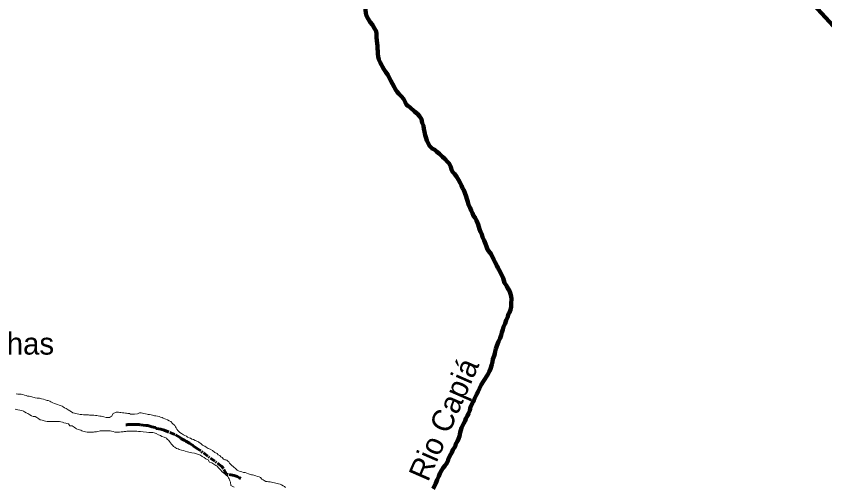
# Model space of a CAD drawing. Extents: x 553962 to 842807, y 8883888 to 9032388.
# Drawn here: x 638188 to 656600, y 8933785 to 8944498 of the extents above; entities that cross this region are included whole.
import ezdxf
from ezdxf.enums import TextEntityAlignment as Align

# ---------------------------------------------------------------- set-up
doc = ezdxf.new("R2010")
doc.units = 0
doc.header["$LTSCALE"] = 20
doc.linetypes.add('LONG_DASH_SHORT_DASH', pattern=[9.9, 6, -1.2, 1.5, -1.2])
for name, color, linetype, lineweight in [('24', 7, 'Continuous', 25), ('25', 7, 'Continuous', 13), ('7', 7, 'LONG_DASH_SHORT_DASH', 60), ('9', 7, 'Continuous', 90)]:
    doc.layers.add(name, color=color, linetype=linetype, lineweight=lineweight)
doc.layers.add('41', color=7, linetype='Continuous')
doc.layers.add('49', color=7, linetype='Continuous')

msp = doc.modelspace()

# ---------------------------------------------------------------- linework, layer by layer
at = {"layer": '24', "lineweight": 53}
for points in [[(645925.12, 8945520.2), (645980.33, 8945480.9), (646030.31, 8945430.92), (646080.29, 8945396.31), (646111.05, 8945361.71), (646137.05, 8945322.55), (646171.76, 8945257.32), (646176.44, 8945189.75), (646181.13, 8945124.68), (646180.83, 8945062.14), (646173.07, 8945007.14), (646162.77, 8944947.15), (646155.03, 8944897.15), (646149.78, 8944847.14), (646141.94, 8944777.13), (646139.17, 8944722.11), (646138.8, 8944644.55), (646145.93, 8944566.96), (646168.16, 8944506.8), (646200.33, 8944434.08), (646247.5, 8944358.79), (646299.76, 8944300.97), (646309.04, 8944284.67)], [(646309.04, 8944284.67), (646346.9, 8944218.17), (646384.15, 8944160.44), (646391.35, 8944097.85), (646395.94, 8944012.77), (646398.11, 8943942.7), (646405.28, 8943872.61), (646412.53, 8943820.04), (646414.72, 8943754.98), (646419.47, 8943702.41), (646424.16, 8943637.34), (646428.88, 8943577.27), (646446.08, 8943512.14), (646475.77, 8943444.43), (646508.03, 8943389.22), (646527.83, 8943344.09), (646562.59, 8943288.87), (646604.79, 8943221.1), (646647.03, 8943160.83), (646684.29, 8943105.6), (646721.45, 8943027.85), (646756.13, 8942957.62), (646790.83, 8942889.89), (646825.57, 8942829.66), (646865.36, 8942779.42), (646902.65, 8942731.69), (646957.43, 8942676.36), (647012.13, 8942606.03), (647046.83, 8942538.29), (647076.57, 8942480.6), (647102.87, 8942459.02), (647151.91, 8942424.72), (647151.91, 8942424.72), (647259.79, 8942331.62), (647323.54, 8942272.81), (647367.67, 8942218.91), (647416.71, 8942155.21), (647431.42, 8942071.9), (647460.84, 8942003.3), (647470.65, 8941934.69), (647485.36, 8941866.09), (647498.58, 8941792.88), (647513.35, 8941742.76), (647537.99, 8941665.08), (647557.79, 8941619.94), (647597.47, 8941547.18), (647657.21, 8941484.32), (647722.12, 8941453.96), (647761.99, 8941421.23), (647826.78, 8941368.35), (647896.49, 8941297.93), (647948.8, 8941250.12), (648011.02, 8941182.25), (648043.36, 8941142.05), (648083.05, 8941071.79), (648100.23, 8941001.64), (648132.5, 8940948.93), (648170.89, 8940907.91), (648214.19, 8940849.18), (648257.5, 8940775), (648294.61, 8940700.82), (648325.54, 8940642.09), (648353.38, 8940586.46), (648378.12, 8940533.92), (648399.77, 8940478.28), (648430.7, 8940394.83), (648446.16, 8940342.28), (648474, 8940274.29), (648489.19, 8940201.48), (648521.39, 8940133.76), (648546.12, 8940073.58), (648581.1, 8940014.64), (648600.57, 8939953.47), (648636.74, 8939906.2), (648667.35, 8939850.59), (648703.52, 8939758.83), (648725.78, 8939700.43), (648739.7, 8939647.6), (648761.96, 8939591.99), (648787, 8939533.6), (648806.47, 8939466.86), (648845.43, 8939394.57), (648873.25, 8939316.71), (648898.3, 8939255.54), (648922.16, 8939185.89), (648969.36, 8939115.59), (649001.71, 8939077.89), (649063.65, 8938952.46), (649095.88, 8938889.74), (649130.59, 8938824.5), (649157.85, 8938769.32), (649200.01, 8938691.53), (649276.83, 8938536), (649291.59, 8938483.38), (649308.84, 8938428.24), (649356.03, 8938355.43), (649380.8, 8938302.76), (649415.62, 8938260.04), (649432.83, 8938197.4), (649457.51, 8938124.71), (649458.67, 8938112.5)], [(649458.67, 8938112.5), (649462.27, 8938074.64), (649461.66, 8937947.03), (649458.86, 8937884.49), (649441.02, 8937814.52), (649418.21, 8937754.59), (649392.98, 8937709.68), (649382.71, 8937654.69), (649342.3, 8937574.82), (649321.94, 8937502.37), (649286.55, 8937427.48), (649266.23, 8937362.53), (649243.4, 8937297.59), (649233.11, 8937237.59), (649207.74, 8937165.16), (649172.36, 8937090.28), (649131.85, 8936990.4), (649111.54, 8936927.95), (649091.23, 8936868), (649088.51, 8936820.47), (649070.74, 8936768.02), (649042.86, 8936693.09), (649035.06, 8936630.58), (649014.73, 8936565.63), (648986.77, 8936473.19), (648966.49, 8936418.24), (648928.61, 8936343.37), (648898.37, 8936298.49), (648858.03, 8936233.64), (648830.29, 8936188.74), (648774.84, 8936103.95), (648736.93, 8936024.08), (648704.07, 8935954.18), (648671.23, 8935886.79), (648635.88, 8935819.41), (648605.56, 8935757.01), (648582.34, 8935707.89)], [(648582.34, 8935707.89), (648534.77, 8935604.74), (648516.88, 8935524.76), (648484.02, 8935454.87), (648466.23, 8935397.41), (648428.44, 8935342.55), (648410.68, 8935290.1), (648377.89, 8935235.22), (648347.58, 8935175.32), (648327.32, 8935125.38), (648299.31, 8935022.93), (648281.39, 8934937.94), (648258.59, 8934878.01), (648238.32, 8934825.56), (648200.51, 8934765.7), (648180.18, 8934700.75), (648132.3, 8934628.43), (648104.46, 8934563.51), (648085.85, 8934528.52)], [(648085.85, 8934528.52), (648033.75, 8934426.25), (648013.45, 8934366.3), (647988.18, 8934313.88), (647947.91, 8934264.04), (647910.14, 8934214.19), (647874.84, 8934156.82), (647836.97, 8934086.95), (647811.67, 8934027.03), (647776.23, 8933942.13), (647745.84, 8933864.72), (647682.69, 8933739.93)]]:
    msp.add_lwpolyline(points, dxfattribs=at)
at = {"layer": '25'}
for points in [[(638186.91, 8935898.35), (638226.9, 8935895.58), (638259.41, 8935895.37), (638281.92, 8935895.22), (638301.93, 8935895.09), (638341.89, 8935887.31), (638376.81, 8935874.57), (638414.23, 8935861.8), (638449.17, 8935851.55), (638486.64, 8935846.3), (638509.11, 8935841.14), (638544.09, 8935835.9), (638566.52, 8935825.74), (638599, 8935820.52), (638621.45, 8935812.86), (638663.91, 8935805.07), (638701.38, 8935799.81), (638721.39, 8935799.68), (638761.31, 8935786.9), (638808.77, 8935779.08), (638851.17, 8935763.77), (638891.11, 8935753.49), (638913.6, 8935750.84), (638950.98, 8935733.07), (638978.38, 8935717.87), (639020.76, 8935700.06), (639058.16, 8935684.79), (639103.07, 8935669.48), (639130.48, 8935656.78), (639170.42, 8935646.5), (639195.36, 8935636.32), (639232.74, 8935618.55), (639260.15, 8935605.85), (639289.99, 8935583.12), (639327.38, 8935565.35), (639349.81, 8935555.19), (639374.67, 8935534.99), (639412.01, 8935512.21), (639444.39, 8935494.48), (639481.73, 8935471.69), (639519.15, 8935458.93), (639544.1, 8935451.26), (639576.56, 8935443.53), (639614.04, 8935438.28), (639646.51, 8935433.05), (639686.49, 8935427.78), (639718.98, 8935425.06), (639738.99, 8935424.93), (639761.5, 8935424.78), (639783.99, 8935422.13), (639814, 8935421.93), (639834.01, 8935421.8), (639856.49, 8935419.14), (639888.99, 8935416.42), (639921.48, 8935413.71), (639956.5, 8935413.48), (639991.47, 8935408.24), (640021.47, 8935405.53), (640053.94, 8935400.32), (640093.9, 8935392.54), (640126.39, 8935389.82), (640148.86, 8935384.67), (640183.82, 8935376.92), (640233.65, 8935364.21), (640316.29, 8935366.03), (640339.19, 8935375.1), (640361.46, 8935385.76), (640394.47, 8935450.64), (640447.22, 8935480.33), (640467.27, 8935485.2), (640487.28, 8935485.07), (640514.77, 8935482.39), (640549.76, 8935479.65), (640572.23, 8935474.49), (640607.22, 8935471.76), (640639.7, 8935466.54), (640677.2, 8935463.78), (640699.69, 8935461.13), (640732.16, 8935455.91), (640767.14, 8935450.67), (640789.57, 8935440.51), (640822.04, 8935435.29), (640842.05, 8935435.15), (640864.56, 8935435.01), (640884.57, 8935434.87), (640947.19, 8935446.98), (640994.86, 8935466.69), (641014.87, 8935466.56), (641037.38, 8935466.41), (641067.35, 8935461.2), (641089.8, 8935453.55), (641132.26, 8935445.75), (641167.23, 8935440.51), (641189.69, 8935432.85), (641224.66, 8935427.62), (641259.62, 8935419.87)], [(638992.5, 8935272.15), (638969.99, 8935272.3), (638924.97, 8935272.59), (638897.48, 8935275.28), (638854.98, 8935278.07), (638825.03, 8935285.77), (638777.64, 8935303.61), (638737.68, 8935311.39), (638700.32, 8935331.66), (638658.05, 8935364.48), (638618.17, 8935382.28), (638573.19, 8935387.58), (638535.79, 8935402.85), (638495.93, 8935423.14), (638451.12, 8935450.98), (638413.76, 8935471.25), (638376.38, 8935489.02), (638351.5, 8935506.71), (638314.1, 8935521.98), (638274.14, 8935529.75), (638224.18, 8935537.6), (638161.77, 8935553.03)], [(641259.62, 8935419.87), (641294.59, 8935414.64), (641334.54, 8935404.36), (641369.51, 8935399.12), (641409.49, 8935393.85), (641441.92, 8935383.62), (641474.32, 8935368.39), (641514.3, 8935363.11), (641536.68, 8935345.44), (641574.08, 8935330.17), (641596.55, 8935325.02), (641636.43, 8935307.23), (641673.81, 8935289.46), (641708.69, 8935271.7), (641748.34, 8935223.87), (641798.06, 8935183.49), (641812.8, 8935148.34), (641832.63, 8935125.67), (641842.45, 8935100.58), (641872.21, 8935067.83), (641894.57, 8935047.65), (641916.88, 8935022.48), (641954.25, 8935002.2), (641994.04, 8934971.89), (642028.91, 8934954.14), (642063.8, 8934936.38), (642086.17, 8934918.71), (642126.04, 8934898.42), (642160.99, 8934890.67), (642188.37, 8934872.97), (642225.79, 8934860.2), (642260.67, 8934842.45), (642283.1, 8934832.29), (642318.02, 8934819.54), (642340.47, 8934811.88), (642357.83, 8934791.74), (642395.17, 8934768.96), (642427.43, 8934736.19), (642462.3, 8934715.94), (642484.75, 8934708.28), (642517.13, 8934690.54), (642539.52, 8934675.37), (642561.91, 8934660.2), (642604.3, 8934642.4), (642661.57, 8934609.47), (642711.25, 8934564.08), (642766.12, 8934543.69), (642790.9, 8934513.48), (642825.78, 8934495.73), (642845.6, 8934470.56), (642875.46, 8934450.33), (642907.72, 8934417.57), (642942.62, 8934402.32), (642965.13, 8934402.17), (642987.58, 8934394.51), (643004.88, 8934366.86), (643027.31, 8934356.7), (643044.57, 8934324.04), (643084.3, 8934286.22), (643146.43, 8934233.24), (643183.71, 8934202.95), (643220.96, 8934167.65), (643253.36, 8934152.42), (643288.22, 8934132.15), (643323.18, 8934124.42), (643363.12, 8934114.14), (643405.59, 8934108.85), (643440.51, 8934096.1), (643477.93, 8934083.33), (643500.39, 8934075.67), (643542.79, 8934060.37), (643567.76, 8934055.2), (643602.75, 8934052.47), (643647.64, 8934034.65), (643685.04, 8934019.38), (643717.47, 8934009.15), (643749.88, 8933993.91), (643784.62, 8933958.64), (643814.52, 8933943.42), (643836.89, 8933925.74), (643871.73, 8933902.98), (643899.25, 8933902.8), (643936.74, 8933900.05), (643971.73, 8933897.31), (644004.21, 8933892.09), (644026.66, 8933884.43), (644066.62, 8933876.65), (644096.57, 8933868.95), (644136.55, 8933863.67), (644161.5, 8933856), (644196.42, 8933843.25), (644226.34, 8933830.53), (644263.7, 8933810.26), (644301.06, 8933789.98), (644323.44, 8933772.31)], [(642690.02, 8934297.16), (642645.24, 8934327.5), (642587.87, 8934347.91), (642556.41, 8934400.24), (642504.77, 8934424.32), (642466.9, 8934451.84), (642425.59, 8934475.92), (642384.28, 8934503.44), (642339.53, 8934524.08), (642294.78, 8934534.4), (642294.78, 8934534.4), (642246.58, 8934548.16), (642188.06, 8934561.92), (642151.83, 8934566.09), (642086.9, 8934579.04), (642032.01, 8934596.93), (641994.61, 8934612.2), (641952.15, 8934619.99), (641902.25, 8934635.34), (641874.87, 8934653.05), (641834.89, 8934658.32), (641800.09, 8934686.08), (641770.19, 8934701.3), (641755.38, 8934726.44), (641723.09, 8934756.69), (641698.33, 8934789.41), (641681.03, 8934817.06), (641663.68, 8934837.2), (641628.93, 8934872.48), (641609.07, 8934892.64), (641558.08, 8934912.82), (641506.45, 8934933.46), (641473.64, 8934950.3), (641426.26, 8934968.14), (641376.48, 8935001.01), (641329.08, 8935016.35), (641301.59, 8935019.03), (641254.09, 8935021.85), (641209.09, 8935024.65), (641159.09, 8935027.49), (641081.62, 8935035.51), (641021.63, 8935040.91), (640971.65, 8935046.25), (640936.68, 8935051.49), (640899.18, 8935054.24), (640864.17, 8935054.48), (640841.66, 8935054.62), (640806.64, 8935054.85), (640769.11, 8935052.6), (640744.08, 8935050.26), (640704.04, 8935048.02), (640684, 8935043.15), (640648.97, 8935040.88), (640621.42, 8935036.05), (640578.88, 8935033.83), (640543.85, 8935031.56), (640498.83, 8935031.85), (640471.32, 8935032.04), (640451.31, 8935032.17), (640431.31, 8935032.3), (640393.87, 8935042.57), (640358.93, 8935052.81), (640326.46, 8935058.03), (640229.1, 8935058.34), (640168.92, 8935061.58), (640141.4, 8935061.76), (640098.87, 8935059.54), (640076.3, 8935052.17), (640041.25, 8935047.4), (640016.18, 8935040.05), (639971.11, 8935032.85), (639951.06, 8935027.97), (639898.52, 8935025.81), (639856.01, 8935026.09), (639833.5, 8935026.24), (639801, 8935028.96), (639768.57, 8935039.19), (639738.59, 8935044.39), (639708.66, 8935054.61), (639686.21, 8935062.27), (639663.77, 8935072.43), (639628.86, 8935085.18), (639601.38, 8935090.37), (639563.98, 8935105.64), (639536.59, 8935120.84), (639511.73, 8935141.03), (639489.35, 8935158.7), (639464.46, 8935173.89), (639409.42, 8935171.75), (639379.75, 8935217.01), (639342.31, 8935227.27), (639317.36, 8935234.95), (639274.9, 8935242.74), (639239.98, 8935255.49), (639202.52, 8935263.25), (639177.57, 8935270.92), (639125.05, 8935271.27), (639090.04, 8935271.5), (639050.02, 8935271.76), (639030.01, 8935271.9), (638992.5, 8935272.15)], [(643147.96, 8933777.58), (643078.2, 8933813.1), (643066.29, 8933890.78), (643056.49, 8933918.39), (643046.66, 8933940.98), (643039.35, 8933966.07), (643021.99, 8933986.21), (643004.71, 8934016.37), (642969.97, 8934051.65), (642947.61, 8934071.82), (642910.3, 8934099.61), (642880.5, 8934127.35), (642842.13, 8934169.74), (642842.13, 8934169.74), (642804.27, 8934207.59), (642755.04, 8934260.31), (642734.83, 8934269.32), (642690.02, 8934297.16)]]:
    msp.add_lwpolyline(points, dxfattribs=at)
at = {"layer": '7'}
for points in [[(641349.46, 8935138.46), (641279.56, 8935153.85), (641232.15, 8935166.61), (641182.24, 8935179.38), (641137.25, 8935182.13), (641014.85, 8935197.78), (640987.37, 8935200.44), (640937.37, 8935200.7), (640887.39, 8935203.47), (640847.41, 8935206.18), (640824.91, 8935206.3), (640794.91, 8935206.46), (640772.41, 8935206.58), (640732.39, 8935204.29), (640707.36, 8935199.42), (640683.22, 8935198.45)], [(643306.94, 8933971.4), (643271.74, 8933987.2), (643221.95, 8934017.49), (643154.6, 8934040.37), (642977.34, 8934076.34), (642905.7, 8934204.34), (642868.5, 8934249.58), (642368.47, 8934617.58), (642318.71, 8934652.87), (642216.69, 8934723.48), (642166.92, 8934758.78), (642137.04, 8934776.46), (642047.38, 8934826.98), (642024.98, 8934842.11), (641937.77, 8934885.11), (641922.92, 8934907.71), (641800.89, 8934978.43), (641648.77, 8935034.28), (641556.52, 8935072.3), (641479.18, 8935095.24), (641381.78, 8935110.76), (641349.46, 8935138.46)]]:
    msp.add_lwpolyline(points, dxfattribs=at)
at = {"layer": '9'}
for points in [[(645793.11, 8949290.87), (653495.42, 8947849.96), (659002.11, 8941889.01), (662653.95, 8939737.69), (668185.18, 8933928.8)], [(645925.12, 8945520.2), (645980.33, 8945480.9), (646030.31, 8945430.92), (646080.29, 8945396.31), (646111.05, 8945361.71), (646137.05, 8945322.55), (646171.76, 8945257.32), (646176.44, 8945189.75), (646181.13, 8945124.68), (646180.83, 8945062.14), (646173.07, 8945007.14), (646162.77, 8944947.15), (646155.03, 8944897.15), (646149.78, 8944847.14), (646141.94, 8944777.13), (646139.17, 8944722.11), (646138.8, 8944644.55), (646145.93, 8944566.96), (646168.16, 8944506.8), (646200.33, 8944434.08), (646247.5, 8944358.79), (646299.76, 8944300.97), (646309.04, 8944284.67)], [(646309.04, 8944284.67), (646346.9, 8944218.17), (646384.15, 8944160.44), (646391.35, 8944097.85), (646395.94, 8944012.77), (646398.11, 8943942.7), (646405.28, 8943872.61), (646412.53, 8943820.04), (646414.72, 8943754.98), (646419.47, 8943702.41), (646424.16, 8943637.34), (646428.88, 8943577.27), (646446.08, 8943512.14), (646475.77, 8943444.43), (646508.03, 8943389.22), (646527.83, 8943344.09), (646562.59, 8943288.87), (646604.79, 8943221.1), (646647.03, 8943160.83), (646684.29, 8943105.6), (646721.45, 8943027.85), (646756.13, 8942957.62), (646790.83, 8942889.89), (646825.57, 8942829.66), (646865.36, 8942779.42), (646902.65, 8942731.69), (646957.43, 8942676.36), (647012.13, 8942606.03), (647046.83, 8942538.29), (647076.57, 8942480.6), (647102.87, 8942459.02), (647151.91, 8942424.72), (647151.91, 8942424.72), (647259.79, 8942331.62), (647323.54, 8942272.81), (647367.67, 8942218.91), (647416.71, 8942155.21), (647431.42, 8942071.9), (647460.84, 8942003.3), (647470.65, 8941934.69), (647485.36, 8941866.09), (647498.58, 8941792.88), (647513.35, 8941742.76), (647537.99, 8941665.08), (647557.79, 8941619.94), (647597.47, 8941547.18), (647657.21, 8941484.32), (647722.12, 8941453.96), (647761.99, 8941421.23), (647826.78, 8941368.35), (647896.49, 8941297.93), (647948.8, 8941250.12), (648011.02, 8941182.25), (648043.36, 8941142.05), (648083.05, 8941071.79), (648100.23, 8941001.64), (648132.5, 8940948.93), (648170.89, 8940907.91), (648214.19, 8940849.18), (648257.5, 8940775), (648294.61, 8940700.82), (648325.54, 8940642.09), (648353.38, 8940586.46), (648378.12, 8940533.92), (648399.77, 8940478.28), (648430.7, 8940394.83), (648446.16, 8940342.28), (648474, 8940274.29), (648489.19, 8940201.48), (648521.39, 8940133.76), (648546.12, 8940073.58), (648581.1, 8940014.64), (648600.57, 8939953.47), (648636.74, 8939906.2), (648667.35, 8939850.59), (648703.52, 8939758.83), (648725.78, 8939700.43), (648739.7, 8939647.6), (648761.96, 8939591.99), (648787, 8939533.6), (648806.47, 8939466.86), (648845.43, 8939394.57), (648873.25, 8939316.71), (648898.3, 8939255.54), (648922.16, 8939185.89), (648969.36, 8939115.59), (649001.71, 8939077.89), (649063.65, 8938952.46), (649095.88, 8938889.74), (649130.59, 8938824.5), (649157.85, 8938769.32), (649200.01, 8938691.53), (649276.83, 8938536), (649291.59, 8938483.38), (649308.84, 8938428.24), (649356.03, 8938355.43), (649380.8, 8938302.76), (649415.62, 8938260.04), (649432.83, 8938197.4), (649457.51, 8938124.71), (649458.67, 8938112.5)], [(649458.67, 8938112.5), (649462.27, 8938074.64), (649461.66, 8937947.03), (649458.86, 8937884.49), (649441.02, 8937814.52), (649418.21, 8937754.59), (649392.98, 8937709.68), (649382.71, 8937654.69), (649342.3, 8937574.82), (649321.94, 8937502.37), (649286.55, 8937427.48), (649266.23, 8937362.53), (649243.4, 8937297.59), (649233.11, 8937237.59), (649207.74, 8937165.16), (649172.36, 8937090.28), (649131.85, 8936990.4), (649111.54, 8936927.95), (649091.23, 8936868), (649088.51, 8936820.47), (649070.74, 8936768.02), (649042.86, 8936693.09), (649035.06, 8936630.58), (649014.73, 8936565.63), (648986.77, 8936473.19), (648966.49, 8936418.24), (648928.61, 8936343.37), (648898.37, 8936298.49), (648858.03, 8936233.64), (648830.29, 8936188.74), (648774.84, 8936103.95), (648736.93, 8936024.08), (648704.07, 8935954.18), (648671.23, 8935886.79), (648635.88, 8935819.41), (648605.56, 8935757.01), (648582.34, 8935707.89)], [(648582.34, 8935707.89), (648534.77, 8935604.74), (648516.88, 8935524.76), (648484.02, 8935454.87), (648466.23, 8935397.41), (648428.44, 8935342.55), (648410.68, 8935290.1), (648377.89, 8935235.22), (648347.58, 8935175.32), (648327.32, 8935125.38), (648299.31, 8935022.93), (648281.39, 8934937.94), (648258.59, 8934878.01), (648238.32, 8934825.56), (648200.51, 8934765.7), (648180.18, 8934700.75), (648132.3, 8934628.43), (648104.46, 8934563.51), (648085.85, 8934528.52)], [(648085.85, 8934528.52), (648033.75, 8934426.25), (648013.45, 8934366.3), (647988.18, 8934313.88), (647947.91, 8934264.04), (647910.14, 8934214.19), (647874.84, 8934156.82), (647836.97, 8934086.95), (647811.67, 8934027.03), (647776.23, 8933942.13), (647745.84, 8933864.72), (647682.69, 8933739.93)]]:
    msp.add_lwpolyline(points, dxfattribs=at)
msp.add_spline([(637260.63, 8972975.84), (641524.45, 8971056.24), (652526.05, 8965412.73), (653164.33, 8965062.83), (670790.48, 8953770.1), (686194.04, 8943929.95), (696283.29, 8937647.07)], degree=3, dxfattribs=at)

# ---------------------------------------------------------------- texts
at = {"layer": '41'}
msp.add_text('Piranhas', height=500, dxfattribs=at).set_placement((636412.75, 8936794.89))
at = {"layer": '49'}
msp.add_text('Rio Capiá', height=500, rotation=66.381, dxfattribs=at).set_placement((648152.93, 8935223.91), align=Align.CENTER)

doc.saveas('drawing.dxf')
